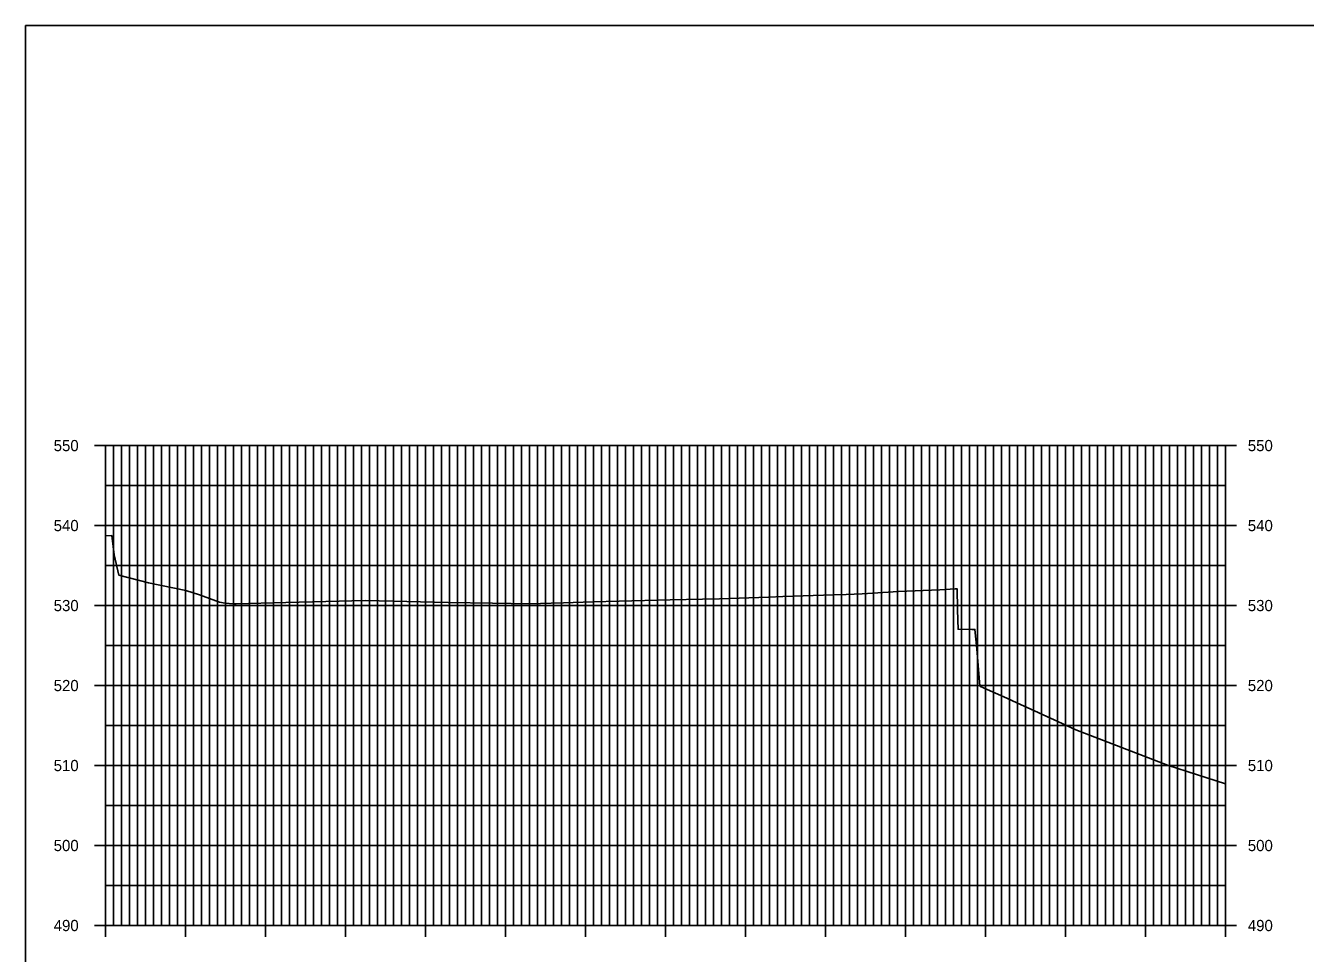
# Model space of a CAD drawing. Extents: x 1509063 to 1512863, y 401160 to 402918.
# Drawn here: x 1510250.9 to 1510410.9, y 402801.9 to 402917.9 of the extents above; entities that cross this region are included whole.
import ezdxf

# ---------------------------------------------------------------- set-up
doc = ezdxf.new("R2010")
doc.units = 0
for name, color, linetype in [('NBL1', 7, 'Continuous'), ('XAX_P', 7, 'Continuous'), ('XAXTIC_P', 7, 'Continuous'), ('XAXTXT_P_T', 7, 'Continuous'), ('XGL_P', 7, 'Continuous'), ('XSLOG', 7, 'Continuous')]:
    doc.layers.add(name, color=color, linetype=linetype)

msp = doc.modelspace()

# ---------------------------------------------------------------- linework, layer by layer
at = {"layer": 'NBL1'}
msp.add_lwpolyline([(1510570.91, 402707.91), (1510250.91, 402707.91), (1510250.91, 402917.91), (1510570.91, 402917.91)], close=True, dxfattribs=at)
at = {"layer": 'XAX_P'}
for p, q in [((1510260.91, 402805.41), (1510260.91, 402865.41)), ((1510330.91, 402805.41), (1510330.91, 402865.41)), ((1510400.91, 402805.41), (1510400.91, 402865.41)), ((1510260.91, 402805.41), (1510400.91, 402805.41))]:
    msp.add_line(p, q, dxfattribs=at)
at = {"layer": 'XAXTIC_P'}
for p, q in [((1510259.51, 402865.41), (1510262.31, 402865.41)), ((1510329.51, 402865.41), (1510332.31, 402865.41)), ((1510402.31, 402865.41), (1510399.51, 402865.41)), ((1510259.51, 402855.41), (1510262.31, 402855.41)), ((1510329.51, 402855.41), (1510332.31, 402855.41)), ((1510402.31, 402855.41), (1510399.51, 402855.41)), ((1510259.51, 402845.41), (1510262.31, 402845.41)), ((1510329.51, 402845.41), (1510332.31, 402845.41)), ((1510402.31, 402845.41), (1510399.51, 402845.41)), ((1510259.51, 402835.41), (1510262.31, 402835.41)), ((1510329.51, 402835.41), (1510332.31, 402835.41)), ((1510402.31, 402835.41), (1510399.51, 402835.41)), ((1510259.51, 402825.41), (1510262.31, 402825.41)), ((1510329.51, 402825.41), (1510332.31, 402825.41)), ((1510402.31, 402825.41), (1510399.51, 402825.41)), ((1510259.51, 402815.41), (1510262.31, 402815.41)), ((1510329.51, 402815.41), (1510332.31, 402815.41)), ((1510402.31, 402815.41), (1510399.51, 402815.41)), ((1510260.91, 402804.01), (1510260.91, 402806.81)), ((1510270.91, 402804.01), (1510270.91, 402806.81)), ((1510280.91, 402804.01), (1510280.91, 402806.81)), ((1510290.91, 402804.01), (1510290.91, 402806.81)), ((1510300.91, 402804.01), (1510300.91, 402806.81)), ((1510310.91, 402804.01), (1510310.91, 402806.81)), ((1510320.91, 402804.01), (1510320.91, 402806.81)), ((1510330.91, 402804.01), (1510330.91, 402806.81)), ((1510340.91, 402804.01), (1510340.91, 402806.81)), ((1510350.91, 402804.01), (1510350.91, 402806.81)), ((1510360.91, 402804.01), (1510360.91, 402806.81)), ((1510370.91, 402804.01), (1510370.91, 402806.81)), ((1510380.91, 402804.01), (1510380.91, 402806.81)), ((1510390.91, 402804.01), (1510390.91, 402806.81)), ((1510400.91, 402804.01), (1510400.91, 402806.81)), ((1510259.51, 402805.41), (1510262.31, 402805.41)), ((1510329.51, 402805.41), (1510332.31, 402805.41)), ((1510402.31, 402805.41), (1510399.51, 402805.41))]:
    msp.add_line(p, q, dxfattribs=at)
at = {"layer": 'XGL_P'}
for p, q in [((1510260.91, 402865.41), (1510400.91, 402865.41)), ((1510260.91, 402805.41), (1510260.91, 402865.41)), ((1510261.91, 402805.41), (1510261.91, 402865.41)), ((1510262.91, 402805.41), (1510262.91, 402865.41)), ((1510263.91, 402805.41), (1510263.91, 402865.41)), ((1510264.91, 402805.41), (1510264.91, 402865.41)), ((1510265.91, 402805.41), (1510265.91, 402865.41)), ((1510266.91, 402805.41), (1510266.91, 402865.41)), ((1510267.91, 402805.41), (1510267.91, 402865.41)), ((1510268.91, 402805.41), (1510268.91, 402865.41)), ((1510269.91, 402805.41), (1510269.91, 402865.41)), ((1510270.91, 402805.41), (1510270.91, 402865.41)), ((1510271.91, 402805.41), (1510271.91, 402865.41)), ((1510272.91, 402805.41), (1510272.91, 402865.41)), ((1510273.91, 402805.41), (1510273.91, 402865.41)), ((1510274.91, 402805.41), (1510274.91, 402865.41)), ((1510275.91, 402805.41), (1510275.91, 402865.41)), ((1510276.91, 402805.41), (1510276.91, 402865.41)), ((1510277.91, 402805.41), (1510277.91, 402865.41)), ((1510278.91, 402805.41), (1510278.91, 402865.41)), ((1510279.91, 402805.41), (1510279.91, 402865.41)), ((1510280.91, 402805.41), (1510280.91, 402865.41)), ((1510281.91, 402805.41), (1510281.91, 402865.41)), ((1510282.91, 402805.41), (1510282.91, 402865.41)), ((1510283.91, 402805.41), (1510283.91, 402865.41)), ((1510284.91, 402805.41), (1510284.91, 402865.41)), ((1510285.91, 402805.41), (1510285.91, 402865.41)), ((1510286.91, 402805.41), (1510286.91, 402865.41)), ((1510287.91, 402805.41), (1510287.91, 402865.41)), ((1510288.91, 402805.41), (1510288.91, 402865.41)), ((1510289.91, 402805.41), (1510289.91, 402865.41)), ((1510290.91, 402805.41), (1510290.91, 402865.41)), ((1510291.91, 402805.41), (1510291.91, 402865.41)), ((1510292.91, 402805.41), (1510292.91, 402865.41)), ((1510293.91, 402805.41), (1510293.91, 402865.41)), ((1510294.91, 402805.41), (1510294.91, 402865.41)), ((1510295.91, 402805.41), (1510295.91, 402865.41)), ((1510296.91, 402805.41), (1510296.91, 402865.41)), ((1510297.91, 402805.41), (1510297.91, 402865.41)), ((1510298.91, 402805.41), (1510298.91, 402865.41)), ((1510299.91, 402805.41), (1510299.91, 402865.41)), ((1510300.91, 402805.41), (1510300.91, 402865.41)), ((1510301.91, 402805.41), (1510301.91, 402865.41)), ((1510302.91, 402805.41), (1510302.91, 402865.41)), ((1510303.91, 402805.41), (1510303.91, 402865.41)), ((1510304.91, 402805.41), (1510304.91, 402865.41)), ((1510305.91, 402805.41), (1510305.91, 402865.41)), ((1510306.91, 402805.41), (1510306.91, 402865.41)), ((1510307.91, 402805.41), (1510307.91, 402865.41)), ((1510308.91, 402805.41), (1510308.91, 402865.41)), ((1510309.91, 402805.41), (1510309.91, 402865.41)), ((1510310.91, 402805.41), (1510310.91, 402865.41)), ((1510311.91, 402805.41), (1510311.91, 402865.41)), ((1510312.91, 402805.41), (1510312.91, 402865.41)), ((1510313.91, 402805.41), (1510313.91, 402865.41)), ((1510314.91, 402805.41), (1510314.91, 402865.41)), ((1510315.91, 402805.41), (1510315.91, 402865.41)), ((1510316.91, 402805.41), (1510316.91, 402865.41)), ((1510317.91, 402805.41), (1510317.91, 402865.41)), ((1510318.91, 402805.41), (1510318.91, 402865.41)), ((1510319.91, 402805.41), (1510319.91, 402865.41)), ((1510320.91, 402805.41), (1510320.91, 402865.41)), ((1510321.91, 402805.41), (1510321.91, 402865.41)), ((1510322.91, 402805.41), (1510322.91, 402865.41)), ((1510323.91, 402805.41), (1510323.91, 402865.41)), ((1510324.91, 402805.41), (1510324.91, 402865.41)), ((1510325.91, 402805.41), (1510325.91, 402865.41)), ((1510326.91, 402805.41), (1510326.91, 402865.41)), ((1510327.91, 402805.41), (1510327.91, 402865.41)), ((1510328.91, 402805.41), (1510328.91, 402865.41)), ((1510329.91, 402805.41), (1510329.91, 402865.41)), ((1510330.91, 402805.41), (1510330.91, 402865.41)), ((1510331.91, 402805.41), (1510331.91, 402865.41)), ((1510332.91, 402805.41), (1510332.91, 402865.41)), ((1510333.91, 402805.41), (1510333.91, 402865.41)), ((1510334.91, 402805.41), (1510334.91, 402865.41)), ((1510335.91, 402805.41), (1510335.91, 402865.41)), ((1510336.91, 402805.41), (1510336.91, 402865.41)), ((1510337.91, 402805.41), (1510337.91, 402865.41)), ((1510338.91, 402805.41), (1510338.91, 402865.41)), ((1510339.91, 402805.41), (1510339.91, 402865.41)), ((1510340.91, 402805.41), (1510340.91, 402865.41)), ((1510341.91, 402805.41), (1510341.91, 402865.41)), ((1510342.91, 402805.41), (1510342.91, 402865.41)), ((1510343.91, 402805.41), (1510343.91, 402865.41)), ((1510344.91, 402805.41), (1510344.91, 402865.41)), ((1510345.91, 402805.41), (1510345.91, 402865.41)), ((1510346.91, 402805.41), (1510346.91, 402865.41)), ((1510347.91, 402805.41), (1510347.91, 402865.41)), ((1510348.91, 402805.41), (1510348.91, 402865.41)), ((1510349.91, 402805.41), (1510349.91, 402865.41)), ((1510350.91, 402805.41), (1510350.91, 402865.41)), ((1510351.91, 402805.41), (1510351.91, 402865.41)), ((1510352.91, 402805.41), (1510352.91, 402865.41)), ((1510353.91, 402805.41), (1510353.91, 402865.41)), ((1510354.91, 402805.41), (1510354.91, 402865.41)), ((1510355.91, 402805.41), (1510355.91, 402865.41)), ((1510356.91, 402805.41), (1510356.91, 402865.41)), ((1510357.91, 402805.41), (1510357.91, 402865.41)), ((1510358.91, 402805.41), (1510358.91, 402865.41)), ((1510359.91, 402805.41), (1510359.91, 402865.41)), ((1510360.91, 402805.41), (1510360.91, 402865.41)), ((1510361.91, 402805.41), (1510361.91, 402865.41)), ((1510362.91, 402805.41), (1510362.91, 402865.41)), ((1510363.91, 402805.41), (1510363.91, 402865.41)), ((1510364.91, 402805.41), (1510364.91, 402865.41)), ((1510365.91, 402805.41), (1510365.91, 402865.41)), ((1510366.91, 402805.41), (1510366.91, 402865.41)), ((1510367.91, 402805.41), (1510367.91, 402865.41)), ((1510368.91, 402805.41), (1510368.91, 402865.41)), ((1510369.91, 402805.41), (1510369.91, 402865.41)), ((1510370.91, 402805.41), (1510370.91, 402865.41)), ((1510371.91, 402805.41), (1510371.91, 402865.41)), ((1510372.91, 402805.41), (1510372.91, 402865.41)), ((1510373.91, 402805.41), (1510373.91, 402865.41)), ((1510374.91, 402805.41), (1510374.91, 402865.41)), ((1510375.91, 402805.41), (1510375.91, 402865.41)), ((1510376.91, 402805.41), (1510376.91, 402865.41)), ((1510377.91, 402805.41), (1510377.91, 402865.41)), ((1510378.91, 402805.41), (1510378.91, 402865.41)), ((1510379.91, 402805.41), (1510379.91, 402865.41)), ((1510380.91, 402805.41), (1510380.91, 402865.41)), ((1510381.91, 402805.41), (1510381.91, 402865.41)), ((1510382.91, 402805.41), (1510382.91, 402865.41)), ((1510383.91, 402805.41), (1510383.91, 402865.41)), ((1510384.91, 402805.41), (1510384.91, 402865.41)), ((1510385.91, 402805.41), (1510385.91, 402865.41)), ((1510386.91, 402805.41), (1510386.91, 402865.41)), ((1510387.91, 402805.41), (1510387.91, 402865.41)), ((1510388.91, 402805.41), (1510388.91, 402865.41)), ((1510389.91, 402805.41), (1510389.91, 402865.41)), ((1510390.91, 402805.41), (1510390.91, 402865.41)), ((1510391.91, 402805.41), (1510391.91, 402865.41)), ((1510392.91, 402805.41), (1510392.91, 402865.41)), ((1510393.91, 402805.41), (1510393.91, 402865.41)), ((1510394.91, 402805.41), (1510394.91, 402865.41)), ((1510395.91, 402805.41), (1510395.91, 402865.41)), ((1510396.91, 402805.41), (1510396.91, 402865.41)), ((1510397.91, 402805.41), (1510397.91, 402865.41)), ((1510398.91, 402805.41), (1510398.91, 402865.41)), ((1510399.91, 402805.41), (1510399.91, 402865.41)), ((1510400.91, 402805.41), (1510400.91, 402865.41)), ((1510260.91, 402860.41), (1510400.91, 402860.41)), ((1510260.91, 402855.41), (1510400.91, 402855.41)), ((1510260.91, 402850.41), (1510400.91, 402850.41)), ((1510260.91, 402845.41), (1510400.91, 402845.41)), ((1510260.91, 402840.41), (1510400.91, 402840.41)), ((1510260.91, 402835.41), (1510400.91, 402835.41)), ((1510260.91, 402830.41), (1510400.91, 402830.41)), ((1510260.91, 402825.41), (1510400.91, 402825.41)), ((1510260.91, 402820.41), (1510400.91, 402820.41)), ((1510260.91, 402815.41), (1510400.91, 402815.41)), ((1510260.91, 402810.41), (1510400.91, 402810.41)), ((1510260.91, 402805.41), (1510400.91, 402805.41))]:
    msp.add_line(p, q, dxfattribs=at)
at = {"layer": 'XSLOG'}
msp.add_lwpolyline([(1510260.91, 402854.13), (1510261.67, 402854.15), (1510261.98, 402851.75), (1510262.58, 402849.22), (1510266.28, 402848.26), (1510270.92, 402847.28), (1510272.66, 402846.73), (1510275.13, 402845.83), (1510275.86, 402845.7), (1510276.89, 402845.63), (1510277.25, 402845.62), (1510283.43, 402845.79), (1510290.13, 402845.95), (1510291.68, 402845.99), (1510293.41, 402846.03), (1510303.74, 402845.78), (1510309.3, 402845.7), (1510313.94, 402845.64), (1510316.63, 402845.72), (1510318.15, 402845.76), (1510321.84, 402845.86), (1510325.13, 402845.94), (1510331.48, 402846.11), (1510335.52, 402846.2), (1510337.67, 402846.26), (1510343.79, 402846.47), (1510345.57, 402846.54), (1510351.9, 402846.75), (1510353.48, 402846.81), (1510355.51, 402846.89), (1510360.03, 402847.17), (1510365.2, 402847.38), (1510367.11, 402847.5), (1510367.39, 402847.48), (1510367.43, 402844.97), (1510367.46, 402843.58), (1510367.49, 402842.44), (1510369.22, 402842.43), (1510369.6, 402842.43), (1510369.81, 402840.01), (1510370.22, 402835.34), (1510370.74, 402835.1), (1510373.19, 402833.99), (1510375.27, 402833.04), (1510377.05, 402832.23), (1510378.59, 402831.53), (1510379.94, 402830.91), (1510381.14, 402830.37), (1510382.2, 402829.88), (1510393.65, 402825.45), (1510400.91, 402823.12)], dxfattribs=at)

# ---------------------------------------------------------------- texts
at = {"layer": 'XAXTXT_P_T'}
for s, p in [('550', (1510254.42, 402864.71)), ('550', (1510403.71, 402864.71)), ('540', (1510254.42, 402854.71)), ('540', (1510403.71, 402854.71)), ('530', (1510254.42, 402844.71)), ('530', (1510403.71, 402844.71)), ('520', (1510254.42, 402834.71)), ('520', (1510403.71, 402834.71)), ('510', (1510254.42, 402824.71)), ('510', (1510403.71, 402824.71)), ('500', (1510254.42, 402814.71)), ('500', (1510403.71, 402814.71)), ('490', (1510254.42, 402804.71)), ('490', (1510403.71, 402804.71))]:
    msp.add_text(s, height=1.4, dxfattribs=at).set_placement(p)

doc.saveas('drawing.dxf')
